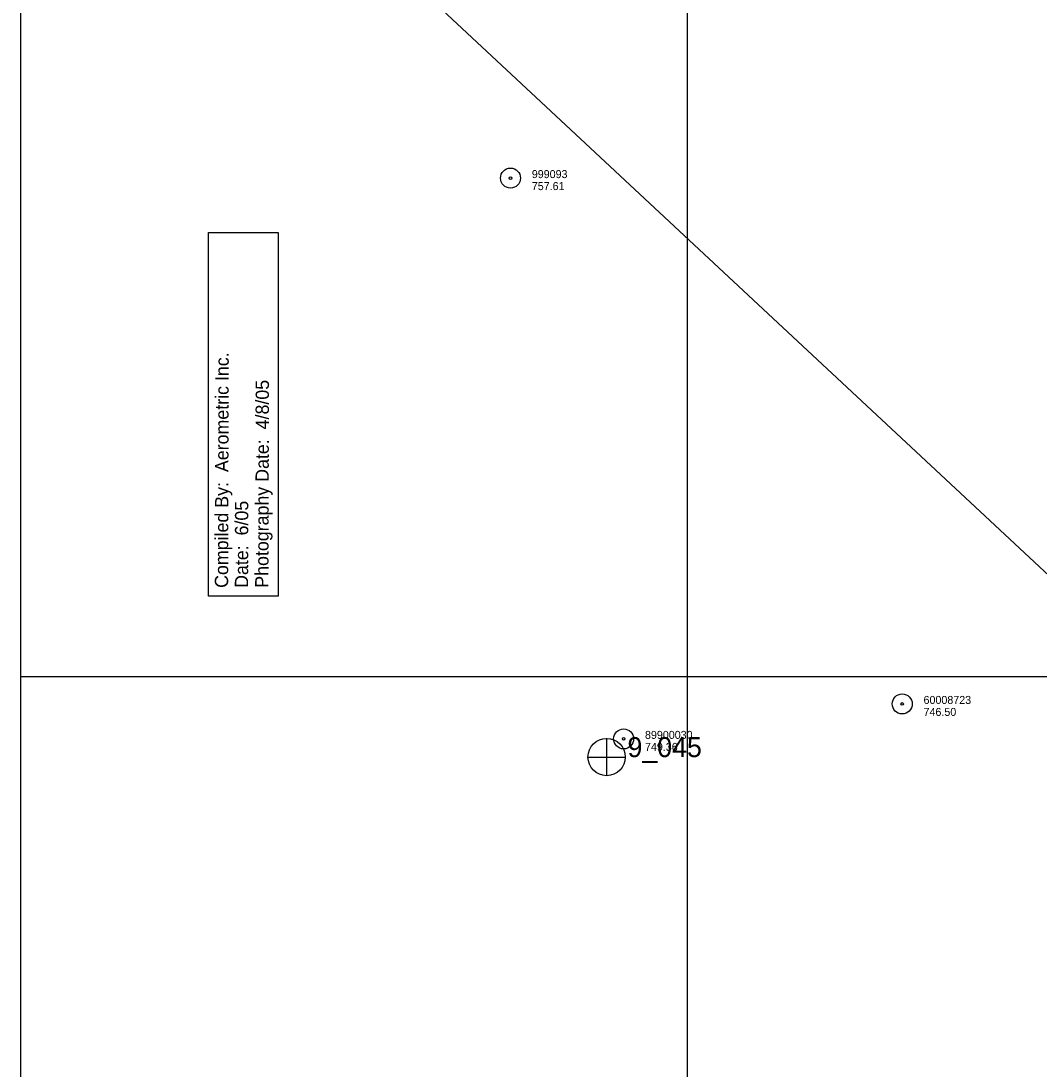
# Model space of a CAD drawing. Extents: x 591954 to 597000, y 198576 to 213500.
# Drawn here: x 592500 to 593264, y 202706 to 203492 of the extents above; entities that cross this region are included whole.
import ezdxf

# ---------------------------------------------------------------- set-up
doc = ezdxf.new("R2010")
doc.units = 0
for name, color, linetype in [('Level 10', 7, 'Continuous'), ('Level 4', 7, 'Continuous'), ('Level 6', 7, 'Continuous')]:
    doc.layers.add(name, color=color, linetype=linetype)

msp = doc.modelspace()

# ---------------------------------------------------------------- linework, layer by layer
at = {"layer": 'Level 10'}
for p, q in [((593000, 203000), (593000, 204500)), ((592500, 202500), (592500, 204000)), ((593000, 202500), (593000, 204000)), ((593000, 202000), (593000, 203500)), ((592500, 203000), (594000, 203000)), ((593000, 203000), (595500, 203000)), ((593000, 203000), (595000, 203000))]:
    msp.add_line(p, q, dxfattribs=at)
msp.add_lwpolyline([(592693.05, 203060.45), (592640.74, 203060.45), (592640.74, 203332.99), (592693.05, 203332.99)], close=True, dxfattribs=at)
at = {"layer": 'Level 4'}
for p, q in [((592939.27, 202953.75), (592939.2, 202925.89)), ((592925.36, 202939.72), (592953.26, 202939.71))]:
    msp.add_line(p, q, dxfattribs=at)
msp.add_lwpolyline([(593556.37, 202809.78), (592771.71, 203541.61), (592770.19, 203809.11)], dxfattribs=at)
msp.add_circle((592939.32, 202939.73), 14, dxfattribs=at)
at = {"layer": 'Level 6'}
for centre, radius in [((592867.19, 203373.89), 7.5), ((592867.19, 203373.89), 0.96), ((593161.03, 202979.53), 7.5), ((593161.03, 202979.53), 7.5), ((593161.03, 202979.53), 7.5), ((593161.03, 202979.53), 0.96), ((593161.03, 202979.53), 0.96), ((593161.03, 202979.53), 0.96), ((592952.08, 202953.32), 7.5), ((592952.08, 202953.32), 0.96)]:
    msp.add_circle(centre, radius, dxfattribs=at)

# ---------------------------------------------------------------- texts
at = {"layer": 'Level 10'}
for s, rotation, p in [('Compiled By:  Aerometric Inc.', 89.8478, (592655.4, 203066.56)), ('Photography Date:  4/8/05  ', 89.84795, (592685.65, 203066.66)), ('Date:  6/05    ', 89.84776, (592670.38, 203066.55))]:
    msp.add_text(s, height=9.986, rotation=rotation, dxfattribs=at).set_placement(p)
at = {"layer": 'Level 4'}
msp.add_text('9_045', height=15, dxfattribs=at).set_placement((592954.97, 202939.66))
at = {"layer": 'Level 6'}
for s, p in [('999093', (592883.19, 203373.89)), ('757.61', (592883.19, 203364.89)), ('60008723', (593177.03, 202979.54)), ('60008723', (593177.03, 202979.54)), ('60008723', (593177.03, 202979.54)), ('746.50', (593177.03, 202970.54)), ('746.50', (593177.03, 202970.54)), ('746.50', (593177.03, 202970.54)), ('89900030', (592968.08, 202953.32)), ('749.36', (592968.08, 202944.32))]:
    msp.add_text(s, height=6, dxfattribs=at).set_placement(p)

doc.saveas('drawing.dxf')
